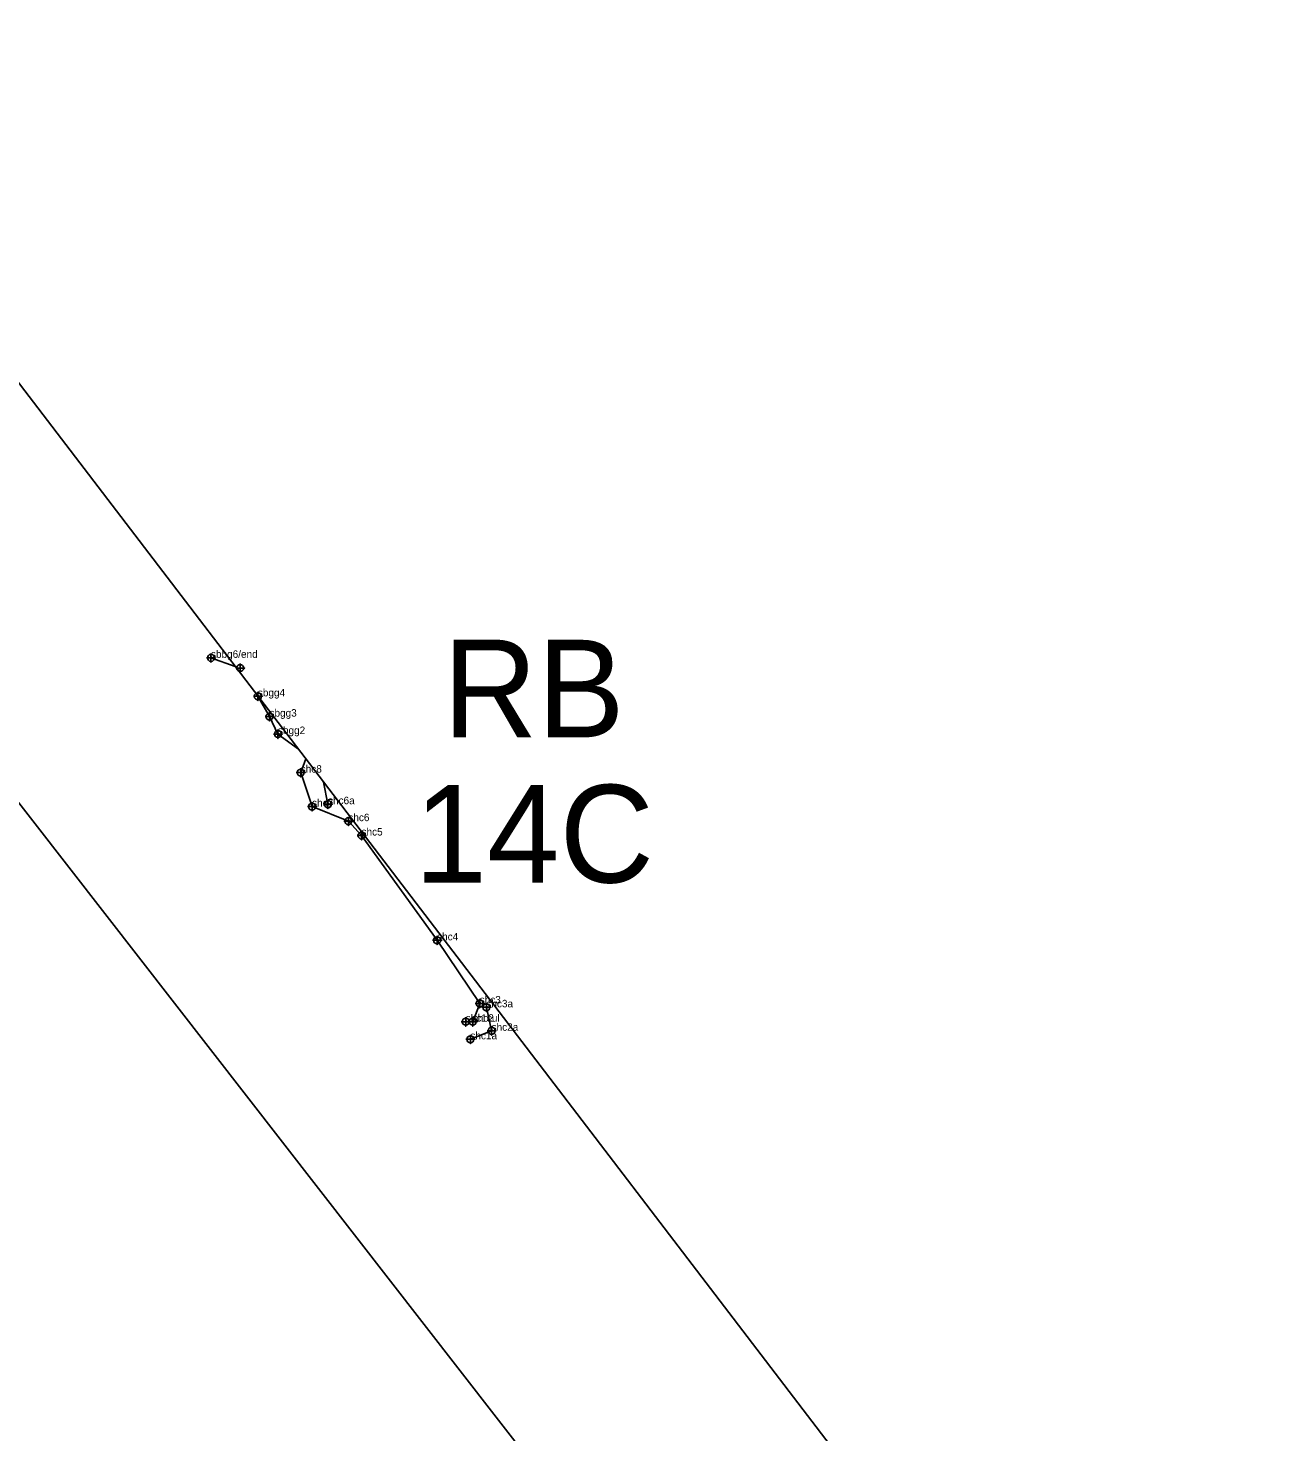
# Model space of a CAD drawing. Extents: x 2071991 to 2268989, y 436479 to 469629.
# Drawn here: x 2207171 to 2208013, y 443712 to 444651 of the extents above; entities that cross this region are included whole.
import ezdxf

# ---------------------------------------------------------------- set-up
doc = ezdxf.new("R2010")
doc.units = 0
for name, color, linetype in [('approx_PSA', 7, 'Continuous'), ('Default', 7, 'Continuous'), ('Exist Hydro Jurisdictional Stream or Body of Water NEU Mitigable', 7, 'Continuous'), ('Exist Hydro Jurisdictional Stream or Body of Water NEU Mitigable Cogo Comment', 7, 'Continuous'), ('Exist Hydro Jurisdictional Stream or Body of Water NEU Mitigable Cogo Point CELL', 7, 'Continuous')]:
    doc.layers.add(name, color=color, linetype=linetype)

msp = doc.modelspace()

# ---------------------------------------------------------------- linework, layer by layer
at = {"layer": 'approx_PSA'}
for p, q in [((2205353.37, 446784.63), (2208012.59, 443304.38)), ((2207685.41, 443463.25), (2207051.74, 444278.53))]:
    msp.add_line(p, q, dxfattribs=at)
at = {"layer": 'Exist Hydro Jurisdictional Stream or Body of Water NEU Mitigable'}
msp.add_line((2207371.74, 444132.12), (2207368.81, 444146.92), dxfattribs=at)
for points in [[(2207293.46, 444230.05), (2207309.63, 444224.37)], [(2207324.19, 444205.32), (2207324.83, 444204.3), (2207332.61, 444190.72), (2207338.27, 444179.07), (2207351.94, 444169)], [(2207463.91, 443986.57), (2207468.56, 443986.59), (2207473.26, 443998.79), (2207444.75, 444041.05), (2207394.18, 444111.17), (2207385.35, 444120.77), (2207361.11, 444130.54), (2207353.48, 444153.25), (2207356.94, 444162.45)], [(2207467.03, 443974.81), (2207481.19, 443980.51), (2207477.7, 443996.21)]]:
    msp.add_lwpolyline(points, dxfattribs=at)
at = {"layer": 'Exist Hydro Jurisdictional Stream or Body of Water NEU Mitigable Cogo Point CELL'}
for points in [[(2207293.46, 444233.05), (2207293.46, 444227.05), (2207293.46, 444230.05), (2207296.46, 444230.05), (2207290.46, 444230.05)], [(2207313, 444226.19), (2207313, 444220.19), (2207313, 444223.19), (2207316, 444223.19), (2207310, 444223.19)], [(2207324.83, 444207.3), (2207324.83, 444201.3), (2207324.83, 444204.3), (2207327.83, 444204.3), (2207321.83, 444204.3)], [(2207332.61, 444193.72), (2207332.61, 444187.72), (2207332.61, 444190.72), (2207335.61, 444190.72), (2207329.61, 444190.72)], [(2207338.27, 444182.07), (2207338.27, 444176.07), (2207338.27, 444179.07), (2207341.27, 444179.07), (2207335.27, 444179.07)], [(2207353.48, 444156.25), (2207353.48, 444150.25), (2207353.48, 444153.25), (2207356.48, 444153.25), (2207350.48, 444153.25)], [(2207361.11, 444133.54), (2207361.11, 444127.54), (2207361.11, 444130.54), (2207364.11, 444130.54), (2207358.11, 444130.54)], [(2207371.74, 444135.12), (2207371.74, 444129.12), (2207371.74, 444132.12), (2207374.74, 444132.12), (2207368.74, 444132.12)], [(2207385.35, 444123.77), (2207385.35, 444117.77), (2207385.35, 444120.77), (2207388.35, 444120.77), (2207382.35, 444120.77)], [(2207394.18, 444114.17), (2207394.18, 444108.17), (2207394.18, 444111.17), (2207397.18, 444111.17), (2207391.18, 444111.17)], [(2207444.75, 444044.05), (2207444.75, 444038.05), (2207444.75, 444041.05), (2207447.75, 444041.05), (2207441.75, 444041.05)], [(2207473.26, 444001.79), (2207473.26, 443995.79), (2207473.26, 443998.79), (2207476.26, 443998.79), (2207470.26, 443998.79)], [(2207477.7, 443999.21), (2207477.7, 443993.21), (2207477.7, 443996.21), (2207480.7, 443996.21), (2207474.7, 443996.21)], [(2207463.91, 443989.57), (2207463.91, 443983.57), (2207463.91, 443986.57), (2207466.91, 443986.57), (2207460.91, 443986.57)], [(2207468.56, 443989.59), (2207468.56, 443983.59), (2207468.56, 443986.59), (2207471.56, 443986.59), (2207465.56, 443986.59)], [(2207467.03, 443977.81), (2207467.03, 443971.81), (2207467.03, 443974.81), (2207470.03, 443974.81), (2207464.03, 443974.81)], [(2207481.19, 443983.51), (2207481.19, 443977.51), (2207481.19, 443980.51), (2207484.19, 443980.51), (2207478.19, 443980.51)]]:
    msp.add_lwpolyline(points, dxfattribs=at)
for centre in [(2207293.46, 444230.05), (2207313, 444223.19), (2207324.83, 444204.3), (2207332.61, 444190.72), (2207338.27, 444179.07), (2207353.48, 444153.25), (2207361.11, 444130.54), (2207371.74, 444132.12), (2207385.35, 444120.77), (2207394.18, 444111.17), (2207444.75, 444041.05), (2207473.26, 443998.79), (2207477.7, 443996.21), (2207463.91, 443986.57), (2207468.56, 443986.59), (2207481.19, 443980.51), (2207467.03, 443974.81)]:
    msp.add_circle(centre, 2.34, dxfattribs=at)

# ---------------------------------------------------------------- texts
at = {"layer": 'Default'}
for s, p in [('RB', (2207448.73, 444176.85)), ('RB', (2207448.73, 444176.85)), ('14C', (2207429.49, 444079.71))]:
    msp.add_text(s, height=65.34, dxfattribs=at).set_placement(p)
at = {"layer": 'Exist Hydro Jurisdictional Stream or Body of Water NEU Mitigable Cogo Comment'}
for s, p in [('sbbg6/end', (2207293.46, 444230.05)), ('sbgg4', (2207324.83, 444204.3)), ('sbgg3', (2207332.61, 444190.72)), ('sbgg2', (2207338.27, 444179.07)), ('shc8', (2207353.48, 444153.25)), ('shc6a', (2207371.74, 444132.12)), ('shc7', (2207361.11, 444130.54)), ('shc6', (2207385.35, 444120.77)), ('shc5', (2207394.18, 444111.17)), ('shc4', (2207444.75, 444041.05)), ('shc3', (2207473.26, 443998.79)), ('shc3a', (2207477.7, 443996.21)), ('shc1cul', (2207463.91, 443986.57)), ('shc2', (2207468.56, 443986.59)), ('shc1a', (2207467.03, 443974.81)), ('shc2a', (2207481.19, 443980.51))]:
    msp.add_text(s, height=5, dxfattribs=at).set_placement(p)

doc.saveas('drawing.dxf')
